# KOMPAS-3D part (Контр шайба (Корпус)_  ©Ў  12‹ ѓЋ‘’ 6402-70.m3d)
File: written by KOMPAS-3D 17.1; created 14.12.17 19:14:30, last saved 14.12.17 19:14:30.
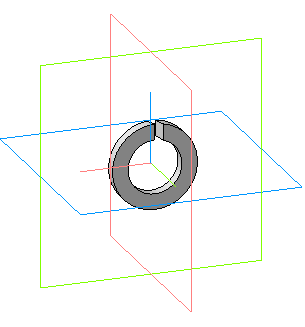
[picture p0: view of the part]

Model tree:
1. Операция без истории:1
